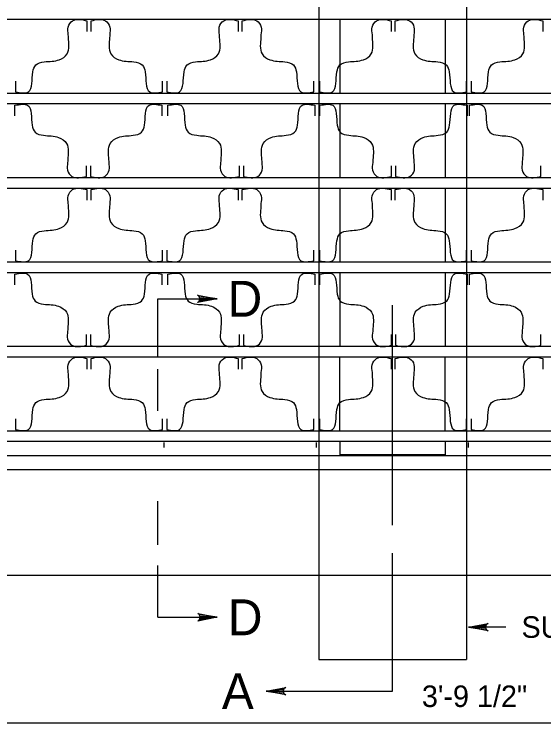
# Model space of a CAD drawing. Extents: x 0.71 to 8.05, y -5.67 to 4.31.
# Drawn here: x 3.555 to 5.033, y 0.134 to 2.109 of the extents above; entities that cross this region are included whole.
import ezdxf

# ---------------------------------------------------------------- set-up
doc = ezdxf.new("R2010")
doc.units = 0
for name, color, linetype in [('DETL-DIMS', 7, 'Continuous'), ('DETL-LINE', 7, 'Continuous'), ('DETL-NOTE', 7, 'Continuous'), ('DETL-TITL', 7, 'Continuous')]:
    doc.layers.add(name, color=color, linetype=linetype)

msp = doc.modelspace()

# ---------------------------------------------------------------- linework, layer by layer
at = {"layer": 'DETL-DIMS'}
for p, q in [((3.956, 1.3161), (4.1214, 1.3161)), ((3.956, 1.1542), (3.956, 1.3161)), ((4.611, 0.6853), (4.611, 1.2987)), ((3.956, 1.0039), (3.956, 1.1197)), ((3.956, 0.6301), (3.956, 0.7516)), ((4.611, 0.2224), (4.611, 0.6072)), ((3.956, 0.4283), (3.956, 0.5729)), ((3.956, 0.4283), (4.1222, 0.4283)), ((4.9266, 0.4011), (4.8227, 0.4011)), ((4.2581, 0.2224), (4.611, 0.2224)), ((2.7098, 0.1342), (6.5122, 0.1342))]:
    msp.add_line(p, q, dxfattribs=at)
for points in [[(4.1214, 1.3161), (4.0665, 1.3058), (4.0708, 1.3088), (4.0729, 1.3124), (4.0736, 1.3161), (4.0729, 1.3198), (4.0708, 1.3235), (4.0665, 1.3264), (4.1214, 1.3161), (4.0708, 1.3235), (4.0729, 1.3198), (4.1214, 1.3161), (4.0736, 1.3161), (4.0729, 1.3124), (4.1214, 1.3161), (4.0708, 1.3088)], [(4.1222, 0.4283), (4.0674, 0.418), (4.0716, 0.421), (4.0738, 0.4246), (4.0744, 0.4283), (4.0738, 0.432), (4.0716, 0.4357), (4.0674, 0.4386), (4.1222, 0.4283), (4.0716, 0.4357), (4.0738, 0.432), (4.1222, 0.4283), (4.0744, 0.4283), (4.0738, 0.4246), (4.1222, 0.4283), (4.0716, 0.421)], [(4.8227, 0.4011), (4.8775, 0.4114), (4.8733, 0.4085), (4.8711, 0.4048), (4.8705, 0.4011), (4.8711, 0.3974), (4.8733, 0.3938), (4.8775, 0.3908), (4.8227, 0.4011), (4.8733, 0.3938), (4.8711, 0.3974), (4.8227, 0.4011), (4.8705, 0.4011), (4.8711, 0.4048), (4.8227, 0.4011), (4.8733, 0.4085)], [(4.2581, 0.2224), (4.3129, 0.2327), (4.3087, 0.2298), (4.3065, 0.2261), (4.3058, 0.2224), (4.3065, 0.2188), (4.3087, 0.2151), (4.3129, 0.2122), (4.2581, 0.2224), (4.3087, 0.2151), (4.3065, 0.2188), (4.2581, 0.2224), (4.3058, 0.2224), (4.3065, 0.2261), (4.2581, 0.2224), (4.3087, 0.2298)]]:
    msp.add_lwpolyline(points, dxfattribs=at)
at = {"layer": 'DETL-LINE'}
for p, q in [((4.4051, 3.4389), (4.4051, 0.3107)), ((4.8169, 3.4389), (4.8169, 0.3107)), ((2.651, 2.0954), (6.571, 2.0954)), ((4.4639, 2.0954), (4.4639, 1.8895)), ((4.7581, 2.0954), (4.7581, 1.8895)), ((3.7586, 2.0909), (3.7586, 2.0615)), ((3.7699, 2.0615), (3.7699, 2.0909)), ((4.1804, 2.0909), (4.1804, 2.0615)), ((4.1917, 2.0615), (4.1917, 2.0909)), ((4.6068, 2.0909), (4.6068, 2.0615)), ((4.6181, 2.0615), (4.6181, 2.0909)), ((5.0298, 2.0909), (5.0298, 2.0615)), ((3.5591, 1.9223), (3.5591, 1.8928)), ((3.9694, 1.8928), (3.9694, 1.9223)), ((3.9809, 1.9223), (3.9809, 1.8928)), ((4.3912, 1.8928), (4.3912, 1.9223)), ((4.4073, 1.9223), (4.4073, 1.8928)), ((4.8176, 1.8928), (4.8176, 1.9223)), ((4.8302, 1.9223), (4.8302, 1.8928)), ((2.651, 1.8895), (6.571, 1.8895)), ((2.651, 1.8601), (6.571, 1.8601)), ((4.4639, 1.8601), (4.4639, 1.6542)), ((4.7581, 1.8601), (4.7581, 1.6542)), ((3.5572, 1.8259), (3.5572, 1.8554)), ((3.9676, 1.8554), (3.9676, 1.8259)), ((3.984, 1.8259), (3.984, 1.8554)), ((4.3944, 1.8554), (4.3944, 1.8259)), ((4.4083, 1.8259), (4.4083, 1.8554)), ((4.8187, 1.8554), (4.8187, 1.8259)), ((4.8255, 1.8259), (4.8255, 1.8554)), ((3.7568, 1.6573), (3.7568, 1.6867)), ((3.768, 1.6867), (3.768, 1.6573)), ((4.1836, 1.6573), (4.1836, 1.6867)), ((4.1948, 1.6867), (4.1948, 1.6573)), ((4.6079, 1.6573), (4.6079, 1.6867)), ((4.6191, 1.6867), (4.6191, 1.6573)), ((5.025, 1.6573), (5.025, 1.6867)), ((2.651, 1.6542), (6.571, 1.6542)), ((2.651, 1.6248), (6.571, 1.6248)), ((3.7586, 1.6203), (3.7586, 1.5909)), ((3.7699, 1.5909), (3.7699, 1.6203)), ((4.1804, 1.6203), (4.1804, 1.5909)), ((4.1917, 1.5909), (4.1917, 1.6203)), ((4.4639, 1.6248), (4.4639, 1.4189)), ((4.6068, 1.6203), (4.6068, 1.5909)), ((4.6181, 1.5909), (4.6181, 1.6203)), ((4.7581, 1.6248), (4.7581, 1.4189)), ((5.0298, 1.6203), (5.0298, 1.5909)), ((3.5591, 1.4517), (3.5591, 1.4222)), ((3.9694, 1.4222), (3.9694, 1.4517)), ((3.9809, 1.4517), (3.9809, 1.4222)), ((4.3912, 1.4222), (4.3912, 1.4517)), ((4.4073, 1.4517), (4.4073, 1.4222)), ((4.8176, 1.4222), (4.8176, 1.4517)), ((4.8302, 1.4517), (4.8302, 1.4222)), ((2.651, 1.4189), (6.571, 1.4189)), ((2.651, 1.3895), (6.571, 1.3895)), ((3.5572, 1.3553), (3.5572, 1.3848)), ((3.9676, 1.3848), (3.9676, 1.3553)), ((3.984, 1.3553), (3.984, 1.3848)), ((4.3944, 1.3848), (4.3944, 1.3553)), ((4.4083, 1.3553), (4.4083, 1.3848)), ((4.4639, 1.3895), (4.4639, 1.1836)), ((4.7581, 1.3895), (4.7581, 1.1836)), ((4.8187, 1.3848), (4.8187, 1.3553)), ((4.8255, 1.3553), (4.8255, 1.3848)), ((3.7568, 1.1867), (3.7568, 1.2161)), ((3.768, 1.2161), (3.768, 1.1867)), ((4.1836, 1.1867), (4.1836, 1.2161)), ((4.1948, 1.2161), (4.1948, 1.1867)), ((4.6079, 1.1867), (4.6079, 1.2161)), ((4.6191, 1.2161), (4.6191, 1.1867)), ((5.025, 1.1867), (5.025, 1.2161)), ((2.651, 1.1836), (6.571, 1.1836)), ((2.651, 1.1542), (6.571, 1.1542)), ((3.7586, 1.1497), (3.7586, 1.1203)), ((3.7699, 1.1203), (3.7699, 1.1497)), ((4.1804, 1.1497), (4.1804, 1.1203)), ((4.1917, 1.1203), (4.1917, 1.1497)), ((4.4639, 0.9483), (4.4639, 1.1542)), ((4.6068, 1.1497), (4.6068, 1.1203)), ((4.6181, 1.1203), (4.6181, 1.1497)), ((4.7581, 0.9483), (4.7581, 1.1542)), ((5.0298, 1.1497), (5.0298, 1.1203)), ((3.5591, 0.9811), (3.5591, 0.9517)), ((3.9694, 0.9517), (3.9694, 0.9811)), ((3.9809, 0.9811), (3.9809, 0.9517)), ((4.3912, 0.9517), (4.3912, 0.9811)), ((4.4073, 0.9811), (4.4073, 0.9517)), ((4.8176, 0.9517), (4.8176, 0.9811)), ((4.8302, 0.9811), (4.8302, 0.9517)), ((2.651, 0.9483), (6.571, 0.9483)), ((2.6116, 0.9189), (6.6104, 0.9189)), ((3.9743, 0.9017), (3.9743, 0.9154)), ((4.3991, 0.9017), (4.3991, 0.9154)), ((4.4639, 0.9189), (4.4639, 0.8795)), ((4.7581, 0.9189), (4.7581, 0.8795)), ((4.8225, 0.9017), (4.8225, 0.9154)), ((2.1992, 0.8795), (7.0228, 0.8795)), ((4.4639, 0.8823), (4.7581, 0.8823)), ((2.1992, 0.8401), (7.0228, 0.8401)), ((2.1992, 0.546), (7.0228, 0.546)), ((4.4051, 0.3107), (4.8169, 0.3107))]:
    msp.add_line(p, q, dxfattribs=at)
for points in [[(3.5591, 1.8928), (3.595, 1.8928), (3.6076, 1.9485), (3.6158, 1.9678), (3.6396, 1.9765), (3.6814, 1.9824), (3.7032, 1.999), (3.7068, 2.0445), (3.7064, 2.0521), (3.7059, 2.0736), (3.7183, 2.0909), (3.7586, 2.0909)], [(3.7699, 2.0909), (3.8102, 2.0909), (3.8226, 2.0736), (3.8221, 2.0521), (3.8217, 2.0445), (3.8253, 1.999), (3.8471, 1.9824), (3.8889, 1.9765), (3.9127, 1.9678), (3.9209, 1.9485), (3.9335, 1.8928), (3.9694, 1.8928)], [(3.9809, 1.8928), (4.0168, 1.8928), (4.0294, 1.9485), (4.0376, 1.9678), (4.0614, 1.9765), (4.1032, 1.9824), (4.125, 1.999), (4.1286, 2.0445), (4.1282, 2.0521), (4.1277, 2.0736), (4.1401, 2.0909), (4.1804, 2.0909)], [(4.1917, 2.0909), (4.232, 2.0909), (4.2444, 2.0736), (4.2439, 2.0521), (4.2435, 2.0445), (4.2471, 1.999), (4.2689, 1.9824), (4.3107, 1.9765), (4.3345, 1.9678), (4.3427, 1.9485), (4.3553, 1.8928), (4.3912, 1.8928)], [(4.4073, 1.8928), (4.4432, 1.8928), (4.4558, 1.9485), (4.464, 1.9678), (4.4878, 1.9765), (4.5296, 1.9824), (4.5514, 1.999), (4.555, 2.0445), (4.5546, 2.0521), (4.5541, 2.0736), (4.5665, 2.0909), (4.6068, 2.0909)], [(4.6181, 2.0909), (4.6584, 2.0909), (4.6708, 2.0736), (4.6703, 2.0521), (4.6699, 2.0445), (4.6735, 1.999), (4.6953, 1.9824), (4.7371, 1.9765), (4.7609, 1.9678), (4.7691, 1.9485), (4.7817, 1.8928), (4.8176, 1.8928)], [(4.8302, 1.8928), (4.8662, 1.8928), (4.8788, 1.9485), (4.8869, 1.9678), (4.9107, 1.9765), (4.9525, 1.9824), (4.9744, 1.999), (4.9779, 2.0445), (4.9775, 2.0521), (4.9771, 2.0736), (4.9894, 2.0909), (5.0298, 2.0909)], [(3.5572, 1.8554), (3.5931, 1.8554), (3.6057, 1.7997), (3.6139, 1.7804), (3.6377, 1.7717), (3.6795, 1.7658), (3.7014, 1.7492), (3.7049, 1.7037), (3.7045, 1.696), (3.704, 1.6746), (3.7164, 1.6573), (3.7568, 1.6573)], [(3.5572, 1.8554), (3.5931, 1.8554), (3.6057, 1.7997), (3.6139, 1.7804), (3.6377, 1.7717), (3.6795, 1.7658), (3.7014, 1.7492), (3.7049, 1.7037), (3.7045, 1.696), (3.704, 1.6746), (3.7164, 1.6573), (3.7568, 1.6573)], [(3.768, 1.6573), (3.8084, 1.6573), (3.8207, 1.6746), (3.8203, 1.696), (3.8198, 1.7037), (3.8234, 1.7492), (3.8453, 1.7658), (3.887, 1.7717), (3.9108, 1.7804), (3.919, 1.7997), (3.9316, 1.8554), (3.9676, 1.8554)], [(3.768, 1.6573), (3.8084, 1.6573), (3.8207, 1.6746), (3.8203, 1.696), (3.8198, 1.7037), (3.8234, 1.7492), (3.8453, 1.7658), (3.887, 1.7717), (3.9108, 1.7804), (3.919, 1.7997), (3.9316, 1.8554), (3.9676, 1.8554)], [(3.984, 1.8554), (4.02, 1.8554), (4.0326, 1.7997), (4.0407, 1.7804), (4.0646, 1.7717), (4.1063, 1.7658), (4.1282, 1.7492), (4.1318, 1.7037), (4.1313, 1.696), (4.1309, 1.6746), (4.1432, 1.6573), (4.1836, 1.6573)], [(3.984, 1.8554), (4.02, 1.8554), (4.0326, 1.7997), (4.0407, 1.7804), (4.0646, 1.7717), (4.1063, 1.7658), (4.1282, 1.7492), (4.1318, 1.7037), (4.1313, 1.696), (4.1309, 1.6746), (4.1432, 1.6573), (4.1836, 1.6573)], [(4.1948, 1.6573), (4.2352, 1.6573), (4.2476, 1.6746), (4.2471, 1.696), (4.2467, 1.7037), (4.2502, 1.7492), (4.2721, 1.7658), (4.3139, 1.7717), (4.3377, 1.7804), (4.3459, 1.7997), (4.3585, 1.8554), (4.3944, 1.8554)], [(4.1948, 1.6573), (4.2352, 1.6573), (4.2476, 1.6746), (4.2471, 1.696), (4.2467, 1.7037), (4.2502, 1.7492), (4.2721, 1.7658), (4.3139, 1.7717), (4.3377, 1.7804), (4.3459, 1.7997), (4.3585, 1.8554), (4.3944, 1.8554)], [(4.4083, 1.8554), (4.4443, 1.8554), (4.4569, 1.7997), (4.4651, 1.7804), (4.4889, 1.7717), (4.5306, 1.7658), (4.5525, 1.7492), (4.5561, 1.7037), (4.5556, 1.696), (4.5552, 1.6746), (4.5675, 1.6573), (4.6079, 1.6573)], [(4.4083, 1.8554), (4.4443, 1.8554), (4.4569, 1.7997), (4.4651, 1.7804), (4.4889, 1.7717), (4.5306, 1.7658), (4.5525, 1.7492), (4.5561, 1.7037), (4.5556, 1.696), (4.5552, 1.6746), (4.5675, 1.6573), (4.6079, 1.6573)], [(4.6191, 1.6573), (4.6595, 1.6573), (4.6719, 1.6746), (4.6714, 1.696), (4.671, 1.7037), (4.6745, 1.7492), (4.6964, 1.7658), (4.7382, 1.7717), (4.762, 1.7804), (4.7702, 1.7997), (4.7828, 1.8554), (4.8187, 1.8554)], [(4.6191, 1.6573), (4.6595, 1.6573), (4.6719, 1.6746), (4.6714, 1.696), (4.671, 1.7037), (4.6745, 1.7492), (4.6964, 1.7658), (4.7382, 1.7717), (4.762, 1.7804), (4.7702, 1.7997), (4.7828, 1.8554), (4.8187, 1.8554)], [(4.8255, 1.8554), (4.8614, 1.8554), (4.874, 1.7997), (4.8822, 1.7804), (4.906, 1.7717), (4.9478, 1.7658), (4.9696, 1.7492), (4.9732, 1.7037), (4.9727, 1.696), (4.9723, 1.6746), (4.9847, 1.6573), (5.025, 1.6573)], [(4.8255, 1.8554), (4.8614, 1.8554), (4.874, 1.7997), (4.8822, 1.7804), (4.906, 1.7717), (4.9478, 1.7658), (4.9696, 1.7492), (4.9732, 1.7037), (4.9727, 1.696), (4.9723, 1.6746), (4.9847, 1.6573), (5.025, 1.6573)], [(3.5591, 1.4222), (3.595, 1.4222), (3.6076, 1.4779), (3.6158, 1.4972), (3.6396, 1.5059), (3.6814, 1.5118), (3.7032, 1.5284), (3.7068, 1.5739), (3.7064, 1.5816), (3.7059, 1.603), (3.7183, 1.6203), (3.7586, 1.6203)], [(3.7699, 1.6203), (3.8102, 1.6203), (3.8226, 1.603), (3.8221, 1.5816), (3.8217, 1.5739), (3.8253, 1.5284), (3.8471, 1.5118), (3.8889, 1.5059), (3.9127, 1.4972), (3.9209, 1.4779), (3.9335, 1.4222), (3.9694, 1.4222)], [(3.9809, 1.4222), (4.0168, 1.4222), (4.0294, 1.4779), (4.0376, 1.4972), (4.0614, 1.5059), (4.1032, 1.5118), (4.125, 1.5284), (4.1286, 1.5739), (4.1282, 1.5816), (4.1277, 1.603), (4.1401, 1.6203), (4.1804, 1.6203)], [(4.1917, 1.6203), (4.232, 1.6203), (4.2444, 1.603), (4.2439, 1.5816), (4.2435, 1.5739), (4.2471, 1.5284), (4.2689, 1.5118), (4.3107, 1.5059), (4.3345, 1.4972), (4.3427, 1.4779), (4.3553, 1.4222), (4.3912, 1.4222)], [(4.4073, 1.4222), (4.4432, 1.4222), (4.4558, 1.4779), (4.464, 1.4972), (4.4878, 1.5059), (4.5296, 1.5118), (4.5514, 1.5284), (4.555, 1.5739), (4.5546, 1.5816), (4.5541, 1.603), (4.5665, 1.6203), (4.6068, 1.6203)], [(4.6181, 1.6203), (4.6584, 1.6203), (4.6708, 1.603), (4.6703, 1.5816), (4.6699, 1.5739), (4.6735, 1.5284), (4.6953, 1.5118), (4.7371, 1.5059), (4.7609, 1.4972), (4.7691, 1.4779), (4.7817, 1.4222), (4.8176, 1.4222)], [(4.8302, 1.4222), (4.8662, 1.4222), (4.8788, 1.4779), (4.8869, 1.4972), (4.9107, 1.5059), (4.9525, 1.5118), (4.9744, 1.5284), (4.9779, 1.5739), (4.9775, 1.5816), (4.9771, 1.603), (4.9894, 1.6203), (5.0298, 1.6203)], [(3.5572, 1.3848), (3.5931, 1.3848), (3.6057, 1.3291), (3.6139, 1.3098), (3.6377, 1.3011), (3.6795, 1.2952), (3.7014, 1.2786), (3.7049, 1.2331), (3.7045, 1.2255), (3.704, 1.204), (3.7164, 1.1867), (3.7568, 1.1867)], [(3.5572, 1.3848), (3.5931, 1.3848), (3.6057, 1.3291), (3.6139, 1.3098), (3.6377, 1.3011), (3.6795, 1.2952), (3.7014, 1.2786), (3.7049, 1.2331), (3.7045, 1.2255), (3.704, 1.204), (3.7164, 1.1867), (3.7568, 1.1867)], [(3.768, 1.1867), (3.8084, 1.1867), (3.8207, 1.204), (3.8203, 1.2255), (3.8198, 1.2331), (3.8234, 1.2786), (3.8453, 1.2952), (3.887, 1.3011), (3.9108, 1.3098), (3.919, 1.3291), (3.9316, 1.3848), (3.9676, 1.3848)], [(3.768, 1.1867), (3.8084, 1.1867), (3.8207, 1.204), (3.8203, 1.2255), (3.8198, 1.2331), (3.8234, 1.2786), (3.8453, 1.2952), (3.887, 1.3011), (3.9108, 1.3098), (3.919, 1.3291), (3.9316, 1.3848), (3.9676, 1.3848)], [(3.984, 1.3848), (4.02, 1.3848), (4.0326, 1.3291), (4.0407, 1.3098), (4.0646, 1.3011), (4.1063, 1.2952), (4.1282, 1.2786), (4.1318, 1.2331), (4.1313, 1.2255), (4.1309, 1.204), (4.1432, 1.1867), (4.1836, 1.1867)], [(3.984, 1.3848), (4.02, 1.3848), (4.0326, 1.3291), (4.0407, 1.3098), (4.0646, 1.3011), (4.1063, 1.2952), (4.1282, 1.2786), (4.1318, 1.2331), (4.1313, 1.2255), (4.1309, 1.204), (4.1432, 1.1867), (4.1836, 1.1867)], [(4.1948, 1.1867), (4.2352, 1.1867), (4.2476, 1.204), (4.2471, 1.2255), (4.2467, 1.2331), (4.2502, 1.2786), (4.2721, 1.2952), (4.3139, 1.3011), (4.3377, 1.3098), (4.3459, 1.3291), (4.3585, 1.3848), (4.3944, 1.3848)], [(4.1948, 1.1867), (4.2352, 1.1867), (4.2476, 1.204), (4.2471, 1.2255), (4.2467, 1.2331), (4.2502, 1.2786), (4.2721, 1.2952), (4.3139, 1.3011), (4.3377, 1.3098), (4.3459, 1.3291), (4.3585, 1.3848), (4.3944, 1.3848)], [(4.4083, 1.3848), (4.4443, 1.3848), (4.4569, 1.3291), (4.4651, 1.3098), (4.4889, 1.3011), (4.5306, 1.2952), (4.5525, 1.2786), (4.5561, 1.2331), (4.5556, 1.2255), (4.5552, 1.204), (4.5675, 1.1867), (4.6079, 1.1867)], [(4.4083, 1.3848), (4.4443, 1.3848), (4.4569, 1.3291), (4.4651, 1.3098), (4.4889, 1.3011), (4.5306, 1.2952), (4.5525, 1.2786), (4.5561, 1.2331), (4.5556, 1.2255), (4.5552, 1.204), (4.5675, 1.1867), (4.6079, 1.1867)], [(4.6191, 1.1867), (4.6595, 1.1867), (4.6719, 1.204), (4.6714, 1.2255), (4.671, 1.2331), (4.6745, 1.2786), (4.6964, 1.2952), (4.7382, 1.3011), (4.762, 1.3098), (4.7702, 1.3291), (4.7828, 1.3848), (4.8187, 1.3848)], [(4.6191, 1.1867), (4.6595, 1.1867), (4.6719, 1.204), (4.6714, 1.2255), (4.671, 1.2331), (4.6745, 1.2786), (4.6964, 1.2952), (4.7382, 1.3011), (4.762, 1.3098), (4.7702, 1.3291), (4.7828, 1.3848), (4.8187, 1.3848)], [(4.8255, 1.3848), (4.8614, 1.3848), (4.874, 1.3291), (4.8822, 1.3098), (4.906, 1.3011), (4.9478, 1.2952), (4.9696, 1.2786), (4.9732, 1.2331), (4.9727, 1.2255), (4.9723, 1.204), (4.9847, 1.1867), (5.025, 1.1867)], [(4.8255, 1.3848), (4.8614, 1.3848), (4.874, 1.3291), (4.8822, 1.3098), (4.906, 1.3011), (4.9478, 1.2952), (4.9696, 1.2786), (4.9732, 1.2331), (4.9727, 1.2255), (4.9723, 1.204), (4.9847, 1.1867), (5.025, 1.1867)], [(3.5591, 0.9517), (3.595, 0.9516), (3.6076, 1.0073), (3.6158, 1.0266), (3.6396, 1.0353), (3.6814, 1.0412), (3.7032, 1.0578), (3.7068, 1.1033), (3.7064, 1.111), (3.7059, 1.1324), (3.7183, 1.1497), (3.7586, 1.1497)], [(3.7699, 1.1497), (3.8102, 1.1497), (3.8226, 1.1324), (3.8221, 1.111), (3.8217, 1.1033), (3.8253, 1.0578), (3.8471, 1.0412), (3.8889, 1.0353), (3.9127, 1.0266), (3.9209, 1.0073), (3.9335, 0.9516), (3.9694, 0.9517)], [(3.9809, 0.9517), (4.0168, 0.9516), (4.0294, 1.0073), (4.0376, 1.0266), (4.0614, 1.0353), (4.1032, 1.0412), (4.125, 1.0578), (4.1286, 1.1033), (4.1282, 1.111), (4.1277, 1.1324), (4.1401, 1.1497), (4.1804, 1.1497)], [(4.1917, 1.1497), (4.232, 1.1497), (4.2444, 1.1324), (4.2439, 1.111), (4.2435, 1.1033), (4.2471, 1.0578), (4.2689, 1.0412), (4.3107, 1.0353), (4.3345, 1.0266), (4.3427, 1.0073), (4.3553, 0.9516), (4.3912, 0.9517)], [(4.4073, 0.9517), (4.4432, 0.9516), (4.4558, 1.0073), (4.464, 1.0266), (4.4878, 1.0353), (4.5296, 1.0412), (4.5514, 1.0578), (4.555, 1.1033), (4.5546, 1.111), (4.5541, 1.1324), (4.5665, 1.1497), (4.6068, 1.1497)], [(4.6181, 1.1497), (4.6584, 1.1497), (4.6708, 1.1324), (4.6703, 1.111), (4.6699, 1.1033), (4.6735, 1.0578), (4.6953, 1.0412), (4.7371, 1.0353), (4.7609, 1.0266), (4.7691, 1.0073), (4.7817, 0.9516), (4.8176, 0.9517)], [(4.8302, 0.9517), (4.8662, 0.9516), (4.8788, 1.0073), (4.8869, 1.0266), (4.9107, 1.0353), (4.9525, 1.0412), (4.9744, 1.0578), (4.9779, 1.1033), (4.9775, 1.111), (4.9771, 1.1324), (4.9894, 1.1497), (5.0298, 1.1497)]]:
    msp.add_spline(points, degree=3, dxfattribs=at)

# ---------------------------------------------------------------- texts
at = {"layer": 'DETL-NOTE'}
for s, p in [('SUPPORT BEAM SEE STD. MD 374.13', (4.9707, 0.3711)), ('3\'-9 1/2"', (4.6929, 0.1783))]:
    msp.add_text(s, height=0.06, dxfattribs=at).set_placement(p)
at = {"layer": 'DETL-TITL'}
for s, p in [('D', (4.1508, 1.2661)), ('D', (4.1516, 0.3783)), ('A', (4.1347, 0.1724))]:
    msp.add_text(s, height=0.1, dxfattribs=at).set_placement(p)

doc.saveas('drawing.dxf')
